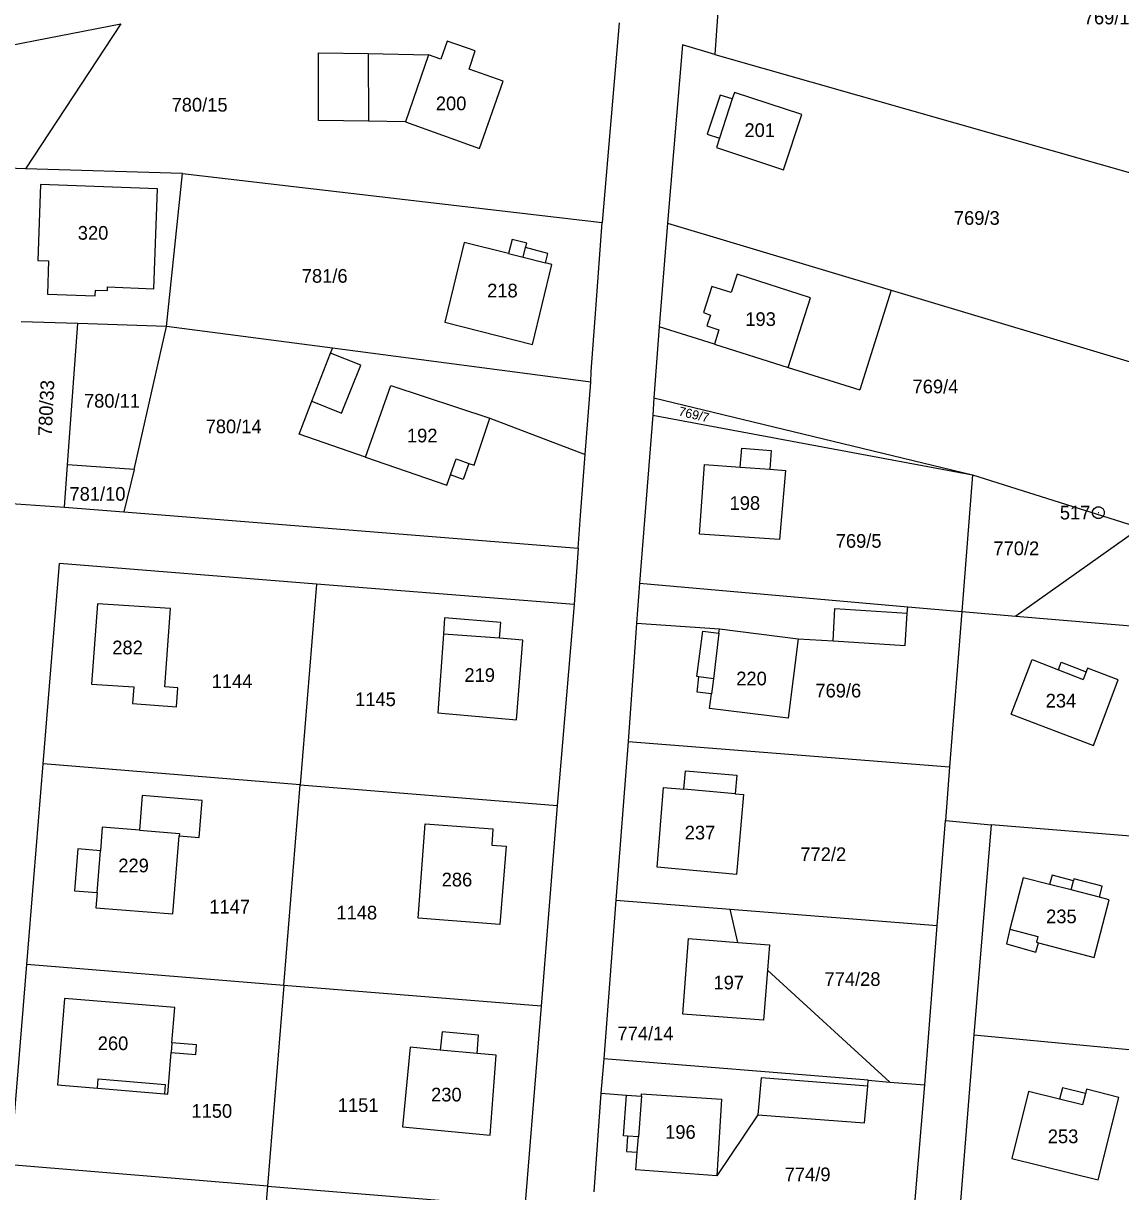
# Model space of a CAD drawing. Extents: x -593358 to -590116, y -1072518 to -1068420.
# Drawn here: x -591930.6 to -591794.4, y -1070702.8 to -1070557.8 of the extents above; entities that cross this region are included whole.
import ezdxf

# ---------------------------------------------------------------- set-up
doc = ezdxf.new("R2010")
doc.units = 0
for name, color, linetype in [('Parcela KN', 7, 'Continuous'), ('Parcela ZE', 7, 'Continuous'), ('Parcelní číslo', 7, 'Continuous'), ('Parcelní číslo_stavební', 7, 'Continuous'), ('stavby - vnitřní kresba', 7, 'Continuous'), ('Vrstva 17', 7, 'Continuous'), ('Vrstva 24', 7, 'Continuous')]:
    doc.layers.add(name, color=color, linetype=linetype)

msp = doc.modelspace()

# ---------------------------------------------------------------- linework, layer by layer
at = {"layer": 'Parcela KN'}
for p, q in [((-591842.66, -1070532.49), (-591844.79, -1070561.62)), ((-591948.67, -1070563.68), (-591918.52, -1070557.84)), ((-591918.52, -1070557.84), (-591930.36, -1070575.81)), ((-591856.66, -1070557.69), (-591858.77, -1070582.47)), ((-591878, -1070559.99), (-591878.82, -1070562.21)), ((-591874.53, -1070561.19), (-591878, -1070559.99)), ((-591848.79, -1070560.43), (-591850.66, -1070582.58)), ((-591844.79, -1070561.62), (-591848.79, -1070560.43)), ((-591893.98, -1070569.84), (-591894, -1070561.41)), ((-591894, -1070561.41), (-591887.82, -1070561.52)), ((-591887.82, -1070561.52), (-591880.33, -1070561.66)), ((-591878.82, -1070562.21), (-591880.33, -1070561.66)), ((-591875.28, -1070563.44), (-591874.53, -1070561.19)), ((-591844.79, -1070561.62), (-591771.38, -1070582.52)), ((-591871.06, -1070564.93), (-591875.28, -1070563.44)), ((-591874.02, -1070573.29), (-591871.06, -1070564.93)), ((-591842.36, -1070566.34), (-591842.64, -1070567.12)), ((-591833.97, -1070569.06), (-591842.36, -1070566.34)), ((-591844.11, -1070566.66), (-591845.72, -1070571.5)), ((-591842.64, -1070567.12), (-591844.11, -1070566.66)), ((-591836.27, -1070575.93), (-591833.97, -1070569.06)), ((-591887.8, -1070569.92), (-591893.98, -1070569.84)), ((-591883.19, -1070569.98), (-591887.8, -1070569.92)), ((-591883.19, -1070569.98), (-591874.02, -1070573.29)), ((-591845.72, -1070571.5), (-591844.19, -1070572.01)), ((-591844.19, -1070572.01), (-591844.58, -1070573.16)), ((-591844.58, -1070573.16), (-591836.27, -1070575.93)), ((-591930.36, -1070575.81), (-591943.2, -1070575.44)), ((-591910.87, -1070576.39), (-591930.36, -1070575.81)), ((-591912.87, -1070595.38), (-591910.87, -1070576.39)), ((-591910.87, -1070576.39), (-591858.77, -1070582.47)), ((-591928.48, -1070577.75), (-591928.81, -1070587.21)), ((-591913.97, -1070578.29), (-591928.48, -1070577.75)), ((-591914.43, -1070590.72), (-591913.97, -1070578.29)), ((-591859.55, -1070593.26), (-591858.77, -1070582.47)), ((-591850.66, -1070582.58), (-591851.68, -1070595.44)), ((-591850.66, -1070582.58), (-591822.9, -1070590.9)), ((-591875.91, -1070584.96), (-591878.31, -1070594.87)), ((-591870.39, -1070586.35), (-591875.91, -1070584.96)), ((-591869.95, -1070584.6), (-591870.39, -1070586.35)), ((-591868.14, -1070585.06), (-591869.95, -1070584.6)), ((-591868.27, -1070585.59), (-591868.14, -1070585.06)), ((-591865.53, -1070586.33), (-591868.27, -1070585.59)), ((-591865.82, -1070587.49), (-591865.53, -1070586.33)), ((-591928.81, -1070587.21), (-591927.5, -1070587.26)), ((-591927.5, -1070587.26), (-591927.64, -1070591.36)), ((-591867.43, -1070597.62), (-591865.04, -1070587.69)), ((-591865.04, -1070587.69), (-591865.82, -1070587.49)), ((-591921.72, -1070591.58), (-591921.69, -1070590.87)), ((-591921.69, -1070590.87), (-591920.19, -1070590.92)), ((-591920.19, -1070590.92), (-591920.18, -1070590.47)), ((-591920.18, -1070590.47), (-591914.43, -1070590.72)), ((-591822.9, -1070590.9), (-591826.8, -1070603.27)), ((-591822.9, -1070590.9), (-591773.67, -1070605.64)), ((-591927.64, -1070591.36), (-591921.72, -1070591.58)), ((-591860.13, -1070600.99), (-591859.55, -1070593.26)), ((-591923.86, -1070595.03), (-591930.89, -1070594.8)), ((-591925.14, -1070612.58), (-591923.86, -1070595.03)), ((-591912.87, -1070595.38), (-591923.86, -1070595.03)), ((-591916.89, -1070613.13), (-591912.87, -1070595.38)), ((-591892.25, -1070598.09), (-591912.87, -1070595.38)), ((-591878.31, -1070594.87), (-591867.43, -1070597.62)), ((-591851.68, -1070595.44), (-591852.35, -1070604.25)), ((-591844.84, -1070597.6), (-591851.68, -1070595.44)), ((-591892.48, -1070598.69), (-591892.25, -1070598.09)), ((-591860.2, -1070602.32), (-591892.25, -1070598.09)), ((-591844.84, -1070597.6), (-591835.7, -1070600.48)), ((-591894.81, -1070604.68), (-591892.48, -1070598.69)), ((-591860.2, -1070602.32), (-591860.13, -1070600.99)), ((-591835.7, -1070600.48), (-591826.8, -1070603.27)), ((-591860.88, -1070611.27), (-591860.2, -1070602.32)), ((-591852.35, -1070604.25), (-591852.49, -1070606.39)), ((-591852.35, -1070604.25), (-591812.8, -1070613.8)), ((-591896.4, -1070608.76), (-591894.81, -1070604.68)), ((-591874.65, -1070612.6), (-591872.71, -1070606.76)), ((-591872.71, -1070606.76), (-591860.88, -1070611.27)), ((-591852.49, -1070606.39), (-591854.14, -1070627.26)), ((-591852.49, -1070606.39), (-591812.8, -1070613.8)), ((-591888.17, -1070611.6), (-591896.4, -1070608.76)), ((-591888.17, -1070611.6), (-591878.05, -1070615.07)), ((-591861.45, -1070618.87), (-591860.88, -1070611.27)), ((-591841.65, -1070612.84), (-591841.45, -1070610.5)), ((-591841.45, -1070610.5), (-591837.78, -1070610.77)), ((-591837.78, -1070610.77), (-591837.95, -1070613.11)), ((-591925.53, -1070617.84), (-591925.14, -1070612.58)), ((-591916.89, -1070613.13), (-591925.14, -1070612.58)), ((-591875.31, -1070612.38), (-591876.02, -1070614.37)), ((-591875.31, -1070612.38), (-591874.65, -1070612.6)), ((-591846.69, -1070621.16), (-591846.05, -1070612.51)), ((-591846.05, -1070612.51), (-591841.65, -1070612.84)), ((-591916.89, -1070613.13), (-591918.14, -1070618.38)), ((-591878.05, -1070615.07), (-591877.6, -1070613.81)), ((-591876.02, -1070614.37), (-591877.6, -1070613.81)), ((-591837.95, -1070613.11), (-591836.01, -1070613.26)), ((-591836.01, -1070613.26), (-591836.76, -1070621.83)), ((-591812.8, -1070613.8), (-591814.13, -1070630.78)), ((-591812.8, -1070613.8), (-591791.96, -1070620.4)), ((-591932.7, -1070617.32), (-591925.53, -1070617.84)), ((-591925.53, -1070617.84), (-591918.14, -1070618.38)), ((-591918.14, -1070618.38), (-591861.75, -1070622.92)), ((-591861.75, -1070622.92), (-591861.45, -1070618.87)), ((-591836.76, -1070621.83), (-591846.69, -1070621.16)), ((-591861.75, -1070622.92), (-591862.23, -1070629.9)), ((-591928.17, -1070649.7), (-591926.15, -1070624.82)), ((-591894.24, -1070627.36), (-591926.15, -1070624.82)), ((-591894.24, -1070627.36), (-591896.27, -1070652.27)), ((-591862.23, -1070629.9), (-591894.24, -1070627.36)), ((-591854.14, -1070627.26), (-591854.49, -1070632.2)), ((-591854.14, -1070627.26), (-591820.84, -1070630.19)), ((-591921.41, -1070629.8), (-591922.18, -1070639.8)), ((-591912.38, -1070630.41), (-591921.41, -1070629.8)), ((-591913.08, -1070640.13), (-591912.38, -1070630.41)), ((-591862.23, -1070629.9), (-591864.34, -1070654.84)), ((-591820.89, -1070630.97), (-591820.84, -1070630.19)), ((-591820.84, -1070630.19), (-591814.13, -1070630.78)), ((-591878.33, -1070631.57), (-591878.48, -1070633.58)), ((-591871.34, -1070632.14), (-591878.33, -1070631.57)), ((-591821.15, -1070634.98), (-591820.89, -1070630.97)), ((-591814.13, -1070630.78), (-591815.64, -1070650.07)), ((-591814.13, -1070630.78), (-591807.41, -1070631.34)), ((-591807.41, -1070631.34), (-591784.25, -1070633.28)), ((-591871.5, -1070634.1), (-591871.34, -1070632.14)), ((-591854.49, -1070632.2), (-591854.83, -1070637.02)), ((-591854.49, -1070632.2), (-591844.21, -1070632.92)), ((-591847.01, -1070638.86), (-591846.26, -1070633.22)), ((-591846.26, -1070633.22), (-591844.28, -1070633.47)), ((-591844.28, -1070633.47), (-591844.21, -1070632.92)), ((-591878.48, -1070633.58), (-591879.18, -1070643.34)), ((-591868.64, -1070634.34), (-591871.5, -1070634.1)), ((-591869.42, -1070644.21), (-591868.64, -1070634.34)), ((-591834.43, -1070634.15), (-591835.68, -1070644.03)), ((-591834.43, -1070634.15), (-591830.09, -1070634.42)), ((-591830.09, -1070634.42), (-591821.15, -1070634.98)), ((-591854.83, -1070637.02), (-591855.56, -1070646.91)), ((-591808.02, -1070643.51), (-591805.4, -1070636.75)), ((-591805.4, -1070636.75), (-591802.14, -1070638.02)), ((-591802.14, -1070638.02), (-591801.78, -1070637.08)), ((-591801.78, -1070637.08), (-591798.7, -1070638.28)), ((-591846.77, -1070638.89), (-591847.01, -1070638.86)), ((-591846.97, -1070640.78), (-591846.77, -1070638.89)), ((-591798.53, -1070637.81), (-591798.7, -1070638.28)), ((-591794.7, -1070639.27), (-591798.53, -1070637.81)), ((-591922.18, -1070639.8), (-591916.93, -1070640.12)), ((-591916.93, -1070640.12), (-591917.07, -1070642.2)), ((-591911.44, -1070640.25), (-591913.08, -1070640.13)), ((-591911.61, -1070642.6), (-591911.44, -1070640.25)), ((-591797.79, -1070647.4), (-591794.7, -1070639.27)), ((-591845.2, -1070641), (-591846.97, -1070640.78)), ((-591845.46, -1070642.8), (-591845.2, -1070641)), ((-591917.07, -1070642.2), (-591911.61, -1070642.6)), ((-591879.18, -1070643.34), (-591869.42, -1070644.21)), ((-591835.68, -1070644.03), (-591845.46, -1070642.8)), ((-591808.02, -1070643.51), (-591797.79, -1070647.4)), ((-591855.56, -1070646.91), (-591857.09, -1070666.6)), ((-591855.56, -1070646.91), (-591815.64, -1070650.07)), ((-591930.19, -1070674.58), (-591928.17, -1070649.7)), ((-591896.27, -1070652.27), (-591928.17, -1070649.7)), ((-591848.62, -1070652.84), (-591848.43, -1070650.55)), ((-591848.43, -1070650.55), (-591842.05, -1070651.07)), ((-591815.64, -1070650.07), (-591816.16, -1070656.7)), ((-591842.05, -1070651.07), (-591842.26, -1070653.39)), ((-591915.88, -1070653.61), (-591916.22, -1070657.91)), ((-591908.44, -1070654.22), (-591915.88, -1070653.61)), ((-591898.29, -1070677.18), (-591896.27, -1070652.27)), ((-591896.27, -1070652.27), (-591864.34, -1070654.84)), ((-591851.96, -1070662.52), (-591851.16, -1070652.63)), ((-591851.16, -1070652.63), (-591848.62, -1070652.84)), ((-591842.26, -1070653.39), (-591841.21, -1070653.48)), ((-591841.21, -1070653.48), (-591842.11, -1070663.41)), ((-591908.81, -1070658.82), (-591908.44, -1070654.22)), ((-591864.34, -1070654.84), (-591866.36, -1070679.78)), ((-591920.83, -1070657.53), (-591921.07, -1070660.48)), ((-591916.22, -1070657.91), (-591920.83, -1070657.53)), ((-591881.61, -1070668.85), (-591880.73, -1070657.14)), ((-591880.73, -1070657.14), (-591872.34, -1070657.77)), ((-591872.34, -1070657.77), (-591872.49, -1070659.77)), ((-591817.18, -1070669.73), (-591816.16, -1070656.7)), ((-591816.16, -1070656.7), (-591810.49, -1070657.27)), ((-591810.49, -1070657.27), (-591812.63, -1070683.34)), ((-591783.38, -1070659.43), (-591810.49, -1070657.27)), ((-591912.05, -1070668.31), (-591911.27, -1070658.62)), ((-591911.27, -1070658.62), (-591908.81, -1070658.82)), ((-591923.87, -1070660.25), (-591924.29, -1070665.44)), ((-591921.07, -1070660.48), (-591923.87, -1070660.25)), ((-591872.49, -1070659.77), (-591870.67, -1070659.91)), ((-591870.67, -1070659.91), (-591871.48, -1070669.61)), ((-591842.11, -1070663.41), (-591851.96, -1070662.52)), ((-591802.93, -1070663.51), (-591803.23, -1070664.66)), ((-591800.28, -1070664.19), (-591802.93, -1070663.51)), ((-591806.49, -1070663.82), (-591808.16, -1070670.21)), ((-591803.23, -1070664.66), (-591806.49, -1070663.82)), ((-591800.22, -1070663.95), (-591800.28, -1070664.19)), ((-591796.69, -1070664.87), (-591800.22, -1070663.95)), ((-591797.04, -1070666.25), (-591796.69, -1070664.87)), ((-591924.29, -1070665.44), (-591921.48, -1070665.67)), ((-591921.48, -1070665.67), (-591921.63, -1070667.55)), ((-591857.09, -1070666.6), (-591858.58, -1070686.28)), ((-591857.09, -1070666.6), (-591842.88, -1070667.71)), ((-591797.71, -1070673.74), (-591795.83, -1070666.56)), ((-591795.83, -1070666.56), (-591797.04, -1070666.25)), ((-591921.63, -1070667.55), (-591912.05, -1070668.31)), ((-591841.94, -1070671.84), (-591842.88, -1070667.71)), ((-591842.88, -1070667.71), (-591817.18, -1070669.73)), ((-591871.48, -1070669.61), (-591881.61, -1070668.85)), ((-591818.72, -1070689.53), (-591817.18, -1070669.73)), ((-591808.16, -1070670.21), (-591808.58, -1070672.02)), ((-591848.75, -1070680.75), (-591848.05, -1070671.38)), ((-591848.05, -1070671.38), (-591841.94, -1070671.84)), ((-591841.94, -1070671.84), (-591838, -1070672.13)), ((-591838, -1070672.13), (-591838.26, -1070675.29)), ((-591808.58, -1070672.02), (-591804.92, -1070673.06)), ((-591804.92, -1070673.06), (-591804.59, -1070671.89)), ((-591804.59, -1070671.89), (-591797.71, -1070673.74)), ((-591932.21, -1070699.47), (-591930.19, -1070674.58)), ((-591898.29, -1070677.18), (-591930.19, -1070674.58)), ((-591838.26, -1070675.29), (-591838.76, -1070681.5)), ((-591823.08, -1070689.18), (-591838.26, -1070675.29)), ((-591898.29, -1070677.18), (-591900.32, -1070702.09)), ((-591866.36, -1070679.78), (-591898.29, -1070677.18)), ((-591925.51, -1070678.8), (-591926.4, -1070689.53)), ((-591911.82, -1070679.94), (-591925.51, -1070678.8)), ((-591912.18, -1070684.3), (-591911.82, -1070679.94)), ((-591866.36, -1070679.78), (-591868.38, -1070704.72)), ((-591838.76, -1070681.5), (-591848.75, -1070680.75)), ((-591878.65, -1070682.93), (-591878.87, -1070685.22)), ((-591874.13, -1070683.36), (-591878.65, -1070682.93)), ((-591874.31, -1070685.65), (-591874.13, -1070683.36)), ((-591812.63, -1070683.34), (-591814.75, -1070709.74)), ((-591812.63, -1070683.34), (-591783.93, -1070686.03)), ((-591912.71, -1070690.67), (-591912.28, -1070685.51)), ((-591912.28, -1070685.51), (-591909.22, -1070685.76)), ((-591909.13, -1070684.56), (-591912.18, -1070684.3)), ((-591909.22, -1070685.76), (-591909.13, -1070684.56)), ((-591882.62, -1070684.87), (-591883.55, -1070694.75)), ((-591878.87, -1070685.22), (-591882.62, -1070684.87)), ((-591871.92, -1070685.84), (-591874.31, -1070685.65)), ((-591872.69, -1070695.77), (-591871.92, -1070685.84)), ((-591858.58, -1070686.28), (-591858.93, -1070690.57)), ((-591825.75, -1070688.96), (-591858.58, -1070686.28)), ((-591926.4, -1070689.53), (-591921.44, -1070689.94)), ((-591826.19, -1070694.24), (-591825.81, -1070689.69)), ((-591825.81, -1070689.69), (-591825.75, -1070688.96)), ((-591825.75, -1070688.96), (-591823.08, -1070689.18)), ((-591823.08, -1070689.18), (-591818.72, -1070689.53)), ((-591819.9, -1070703.8), (-591818.72, -1070689.53)), ((-591801.63, -1070689.9), (-591801.98, -1070691.32)), ((-591798.79, -1070690.61), (-591801.63, -1070689.9)), ((-591921.44, -1070689.94), (-591913.11, -1070690.64)), ((-591913.11, -1070690.64), (-591912.71, -1070690.67)), ((-591858.93, -1070690.57), (-591859.79, -1070702.79)), ((-591858.93, -1070690.57), (-591855.74, -1070690.83)), ((-591856.13, -1070695.85), (-591855.74, -1070690.83)), ((-591805.84, -1070690.36), (-591807.92, -1070698.67)), ((-591801.98, -1070691.32), (-591805.84, -1070690.36)), ((-591798.66, -1070690.08), (-591798.79, -1070690.61)), ((-591794.64, -1070691.08), (-591798.66, -1070690.08)), ((-591797.2, -1070701.33), (-591794.64, -1070691.08)), ((-591839.46, -1070693.25), (-591844.53, -1070700.83)), ((-591839.46, -1070693.25), (-591826.19, -1070694.24)), ((-591883.55, -1070694.75), (-591872.69, -1070695.77)), ((-591855.63, -1070695.89), (-591856.13, -1070695.85)), ((-591855.63, -1070695.89), (-591855.77, -1070697.8)), ((-591855.77, -1070697.8), (-591854.42, -1070697.9)), ((-591854.58, -1070700.06), (-591854.42, -1070697.9)), ((-591900.32, -1070702.09), (-591932.21, -1070699.47)), ((-591844.53, -1070700.83), (-591854.58, -1070700.06)), ((-591807.92, -1070698.67), (-591797.2, -1070701.33)), ((-591900.32, -1070702.09), (-591902.34, -1070727)), ((-591900.32, -1070702.09), (-591868.38, -1070704.72))]:
    msp.add_line(p, q, dxfattribs=at)
at = {"layer": 'Parcela ZE'}
msp.add_line((-591791.96, -1070620.4), (-591807.41, -1070631.34), dxfattribs=at)
at = {"layer": 'stavby - vnitřní kresba'}
for p, q in [((-591887.82, -1070561.52), (-591887.8, -1070569.92)), ((-591880.33, -1070561.66), (-591883.19, -1070569.98)), ((-591842.64, -1070567.12), (-591844.19, -1070572.01)), ((-591870.39, -1070586.35), (-591868.58, -1070586.8)), ((-591868.58, -1070586.8), (-591868.27, -1070585.59)), ((-591868.58, -1070586.8), (-591865.82, -1070587.49)), ((-591842, -1070588.89), (-591842.75, -1070591.19)), ((-591832.89, -1070591.85), (-591842, -1070588.89)), ((-591845.15, -1070590.41), (-591846.21, -1070593.67)), ((-591842.75, -1070591.19), (-591845.15, -1070590.41)), ((-591835.7, -1070600.48), (-591832.89, -1070591.85)), ((-591846.21, -1070593.67), (-591845.34, -1070593.98)), ((-591845.34, -1070593.98), (-591845.78, -1070595.33)), ((-591845.78, -1070595.33), (-591844.29, -1070595.79)), ((-591844.29, -1070595.79), (-591844.84, -1070597.6)), ((-591888.74, -1070600.19), (-591892.48, -1070598.69)), ((-591891.12, -1070606.15), (-591888.74, -1070600.19)), ((-591888.17, -1070611.6), (-591885, -1070602.71)), ((-591885, -1070602.71), (-591872.71, -1070606.76)), ((-591894.81, -1070604.68), (-591891.12, -1070606.15)), ((-591877.6, -1070613.81), (-591876.89, -1070611.83)), ((-591876.89, -1070611.83), (-591875.31, -1070612.38)), ((-591841.65, -1070612.84), (-591837.95, -1070613.11)), ((-591830.09, -1070634.42), (-591829.87, -1070630.39)), ((-591829.87, -1070630.39), (-591820.89, -1070630.97)), ((-591844.21, -1070632.92), (-591834.43, -1070634.15)), ((-591871.5, -1070634.1), (-591878.48, -1070633.58)), ((-591844.28, -1070633.47), (-591844.97, -1070639.13)), ((-591844.97, -1070639.13), (-591846.77, -1070638.89)), ((-591844.97, -1070639.13), (-591845.2, -1070641)), ((-591802.14, -1070638.02), (-591799.06, -1070639.22)), ((-591798.7, -1070638.28), (-591799.06, -1070639.22)), ((-591842.26, -1070653.39), (-591848.62, -1070652.84)), ((-591916.22, -1070657.91), (-591911.25, -1070658.32)), ((-591911.25, -1070658.32), (-591911.27, -1070658.62)), ((-591921.48, -1070665.67), (-591921.07, -1070660.48)), ((-591800.57, -1070665.34), (-591803.23, -1070664.66)), ((-591800.57, -1070665.34), (-591800.28, -1070664.19)), ((-591797.04, -1070666.25), (-591800.57, -1070665.34)), ((-591808.16, -1070670.21), (-591804.67, -1070671.12)), ((-591804.67, -1070671.12), (-591804.85, -1070671.82)), ((-591804.85, -1070671.82), (-591804.59, -1070671.89)), ((-591912.18, -1070684.3), (-591912.28, -1070685.51)), ((-591874.31, -1070685.65), (-591878.87, -1070685.22)), ((-591921.44, -1070689.94), (-591921.34, -1070688.79)), ((-591921.34, -1070688.79), (-591913.02, -1070689.48)), ((-591913.02, -1070689.48), (-591913.11, -1070690.64)), ((-591839.05, -1070688.64), (-591839.46, -1070693.25)), ((-591825.81, -1070689.69), (-591839.05, -1070688.64)), ((-591855.74, -1070690.83), (-591853.91, -1070690.95)), ((-591853.91, -1070690.95), (-591854.27, -1070696)), ((-591853.91, -1070690.95), (-591853.89, -1070690.65)), ((-591853.89, -1070690.65), (-591843.97, -1070691.29)), ((-591843.97, -1070691.29), (-591844.53, -1070700.83)), ((-591799.15, -1070692.03), (-591801.98, -1070691.32)), ((-591798.79, -1070690.61), (-591799.15, -1070692.03)), ((-591854.27, -1070696), (-591855.63, -1070695.89)), ((-591854.42, -1070697.9), (-591854.27, -1070696))]:
    msp.add_line(p, q, dxfattribs=at)
at = {"layer": 'Vrstva 24'}
msp.add_line((-591797.22, -1070618.5), (-591797.12, -1070618.5), dxfattribs=at)
msp.add_lwpolyline([(-591796.98, -1070617.78), (-591796.64, -1070617.97), (-591796.45, -1070618.31), (-591796.45, -1070618.7), (-591796.64, -1070619.04), (-591796.98, -1070619.23), (-591797.37, -1070619.23), (-591797.71, -1070619.04), (-591797.9, -1070618.7), (-591797.9, -1070618.31), (-591797.71, -1070617.97), (-591797.37, -1070617.78)], close=True, dxfattribs=at)

# ---------------------------------------------------------------- texts
at = {"layer": 'Parcelní číslo'}
for s, p in [('769/1', (-591798.985, -1070557.89)), ('780/15', (-591912.225, -1070568.72)), ('769/3', (-591815.11, -1070582.77)), ('781/6', (-591896.062, -1070589.96)), ('769/4', (-591820.243, -1070603.69)), ('780/11', (-591923.1, -1070605.47)), ('780/14', (-591907.998, -1070608.65)), ('781/10', (-591924.9, -1070617.02)), ('769/5', (-591829.78, -1070622.86)), ('770/2', (-591810.203, -1070623.78)), ('1144', (-591907.247, -1070640.28)), ('769/6', (-591832.303, -1070641.44)), ('1145', (-591889.444, -1070642.52)), ('772/2', (-591834.17, -1070661.75)), ('1147', (-591907.537, -1070668.26)), ('1148', (-591891.767, -1070669)), ('774/28', (-591831.176, -1070677.25)), ('774/14', (-591856.874, -1070684)), ('1151', (-591891.596, -1070692.89)), ('1150', (-591909.761, -1070693.62)), ('774/9', (-591836.113, -1070701.49))]:
    msp.add_text(s, height=1.7, dxfattribs=at).set_placement(p)
for s, height, rotation, p in [('780/33', 1.7, 87.31877, (-591927.102, -1070609.035)), ('769/7', 1.14, 346.81135, (-591849.369, -1070606.437))]:
    msp.add_text(s, height=height, rotation=rotation, dxfattribs=at).set_placement(p)
at = {"layer": 'Parcelní číslo_stavební'}
for s, p in [('200', (-591879.421, -1070568.55)), ('201', (-591841.107, -1070571.87)), ('320', (-591923.872, -1070584.62)), ('218', (-591873.05, -1070591.78)), ('193', (-591841.003, -1070595.33)), ('192', (-591883.01, -1070609.78)), ('198', (-591842.956, -1070618.16)), ('282', (-591919.588, -1070636.09)), ('219', (-591875.87, -1070639.51)), ('220', (-591842.128, -1070639.94)), ('234', (-591803.715, -1070642.69)), ('237', (-591848.525, -1070659.07)), ('229', (-591918.841, -1070663.15)), ('286', (-591878.695, -1070664.9)), ('235', (-591803.662, -1070669.47)), ('197', (-591844.956, -1070677.68)), ('260', (-591921.395, -1070685.22)), ('230', (-591880.012, -1070691.59)), ('196', (-591850.956, -1070696.23)), ('253', (-591803.452, -1070696.77))]:
    msp.add_text(s, height=1.7, dxfattribs=at).set_placement(p)
at = {"layer": 'Vrstva 17'}
msp.add_text('517', height=1.7, dxfattribs=at).set_placement((-591801.96, -1070619.35))

doc.saveas('drawing.dxf')
